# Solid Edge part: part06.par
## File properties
Author: Robert a Rhodes jr
Template: normal.par
Last saved by: Cadcim
Revision: 7
Application: Solid Edge
Accuracy: 0.99
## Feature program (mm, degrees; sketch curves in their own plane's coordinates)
sketch for "unnamed Protrusion 1" plane through (0, 0, 0) normal (0, -1, 0) x-axis (1, 0, 0)
  arc centre (60, 0) radius 30 from (60, 30) to (60, -30) cw
  line (104, -30) -> (60, -30)
  line (104, 18) -> (104, -30)
  line (164, 18) -> (104, 18)
  line (164, -4) -> (164, 18)
  line (182, -4) -> (164, -4)
  line (182, -4) -> (182, 36)
  line (142, 36) -> (182, 36)
  line (142, 30) -> (142, 36)
  line (60, 30) -> (142, 30)
extrude "unnamed Protrusion 1" add finite 54 symmetric
sketch for "ExtrudedProtrusion_6" #1 plane through (0, 0, 0) normal (0, -1, 0) x-axis (1, 0, 0)
  arc centre (60, 0) radius 30 from (60, 30) to (60, -30) ccw
  arc centre (60, 0) radius 30 from (60, 30) to (60, -30) cw
sketch for "ExtrudedProtrusion_6" #2 plane through (0, 0, 0) normal (0, -1, 0) x-axis (1, 0, 0)
  circle centre (60, 0) radius 18
extrude "ExtrudedProtrusion_6" add finite 66 symmetric
sketch for "ExtrudedProtrusion_7" plane through (0, 0, 0) normal (0, -1, 0) x-axis (1, 0, 0)
  line (104, -30) -> (164, -4)
  line (164, -4) -> (164, 18)
  line (164, 18) -> (104, 18)
  line (104, 18) -> (104, -30)
extrude "ExtrudedProtrusion_7" add finite 18 symmetric
sketch for "ExtrudedProtrusion_8" plane through (0, 0, 0) normal (0, -1, 0) x-axis (1, 0, 0)
  line (200, 76) -> (200, -4)
  line (200, -4) -> (182, -4)
  line (182, -4) -> (182, 36)
  line (182, 76) -> (182, 36)
  line (182, 76) -> (200, 76)
extrude "ExtrudedProtrusion_8" add finite 92 symmetric
sketch for "ExtrudedProtrusion_9" plane through (0, 0, 0) normal (0, -1, 0) x-axis (1, 0, 0)
  line (142, 36) -> (182, 76)
  line (182, 76) -> (182, 36)
  line (142, 36) -> (182, 36)
extrude "ExtrudedProtrusion_9" add finite 12 symmetric
sketch for "unnamed Hole 1" plane through (200, 0, 36) normal (1, 0, 0) x-axis (0, 1, 0)
hole "unnamed Hole 1" through
sketch for "Hole_1" plane through (200, 0, 36) normal (1, 0, 0) x-axis (0, 1, 0)
  hole centre (-30, 22) bore radius 8
hole "Hole_1" diameter 16 through
pattern "unnamed Pattern 1" of "unnamed Hole 1", "Hole_1"
fillet "unnamed Round 1"
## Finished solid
Body 1: solid body, 34 faces, 81 edges, 46 vertices.
  Faces by surface: plane 28, cylinder 6
  Edges by curve: line 67, circle 14
Bounding box of the edges (mm): 170.000 x 92.000 x 106.000, from (30, -46, -30) to (200, 46, 76).
Cylindrical faces by radius (mm): R8 x2, R16 x2, R18 x1, R30 x1
Planar faces by outward normal: +x 3, +y 5, +z 4, -x 5, -y 5, -z 4, oblique 2
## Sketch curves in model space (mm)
circle centre (60, 0, 0) radius 18
line (182, 0, -4) -> (164, 0, -4)
line (104, 0, -30) -> (60, 0, -30)
arc centre (60, 0, 0) radius 30 from (60, 0, 30) through (30.0132, 0, -0.889) to (60, 0, -30)
arc centre (60, 0, 0) radius 30 from (60, 0, 30) through (89.9868, 0, -0.889) to (60, 0, -30)
line (142, 0, 36) -> (182, 0, 76)
line (142, 0, 36) -> (182, 0, 36)
line (104, 0, -30) -> (164, 0, -4)
line (182, 0, 76) -> (182, 0, 36)
line (182, 0, -4) -> (182, 0, 36)
line (142, 0, 30) -> (142, 0, 36)
line (60, 0, 30) -> (142, 0, 30)
line (104, 0, 18) -> (104, 0, -30)
line (164, 0, 18) -> (104, 0, 18)
line (164, 0, -4) -> (164, 0, 18)
line (200, 0, -4) -> (182, 0, -4)
line (200, 0, 76) -> (200, 0, -4)
line (182, 0, 76) -> (200, 0, 76)
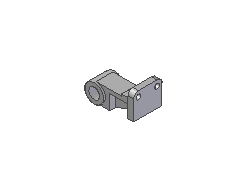
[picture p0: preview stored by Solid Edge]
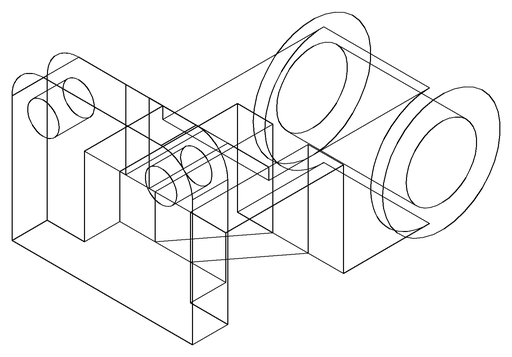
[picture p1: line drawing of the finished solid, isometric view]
